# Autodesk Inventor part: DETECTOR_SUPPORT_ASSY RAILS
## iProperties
Shininess: 64.0
Length Units: 11272
Angle Units: 11279
Time Units: 11290
Mass Units: 11286
Length Display Precision: 3
Angle Display Precision: 2
Compacted: True
Part Number: DETECTOR_SUPPORT_ASSY RAILS
Document SubType Name: Modeling
Created: 2004-08
Designer: John Blackburn
Material: MILD_STEEL
Manufacturer: Standard
Standards Organization: Custom
Density: 0.0
Volumn: 0.0
Area: 0.0
PropertySet Name: Model Information
Control State: 0
Master: False
Checked Out: False
Author: John Blackburn
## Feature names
1. ExtrusionBlind1
